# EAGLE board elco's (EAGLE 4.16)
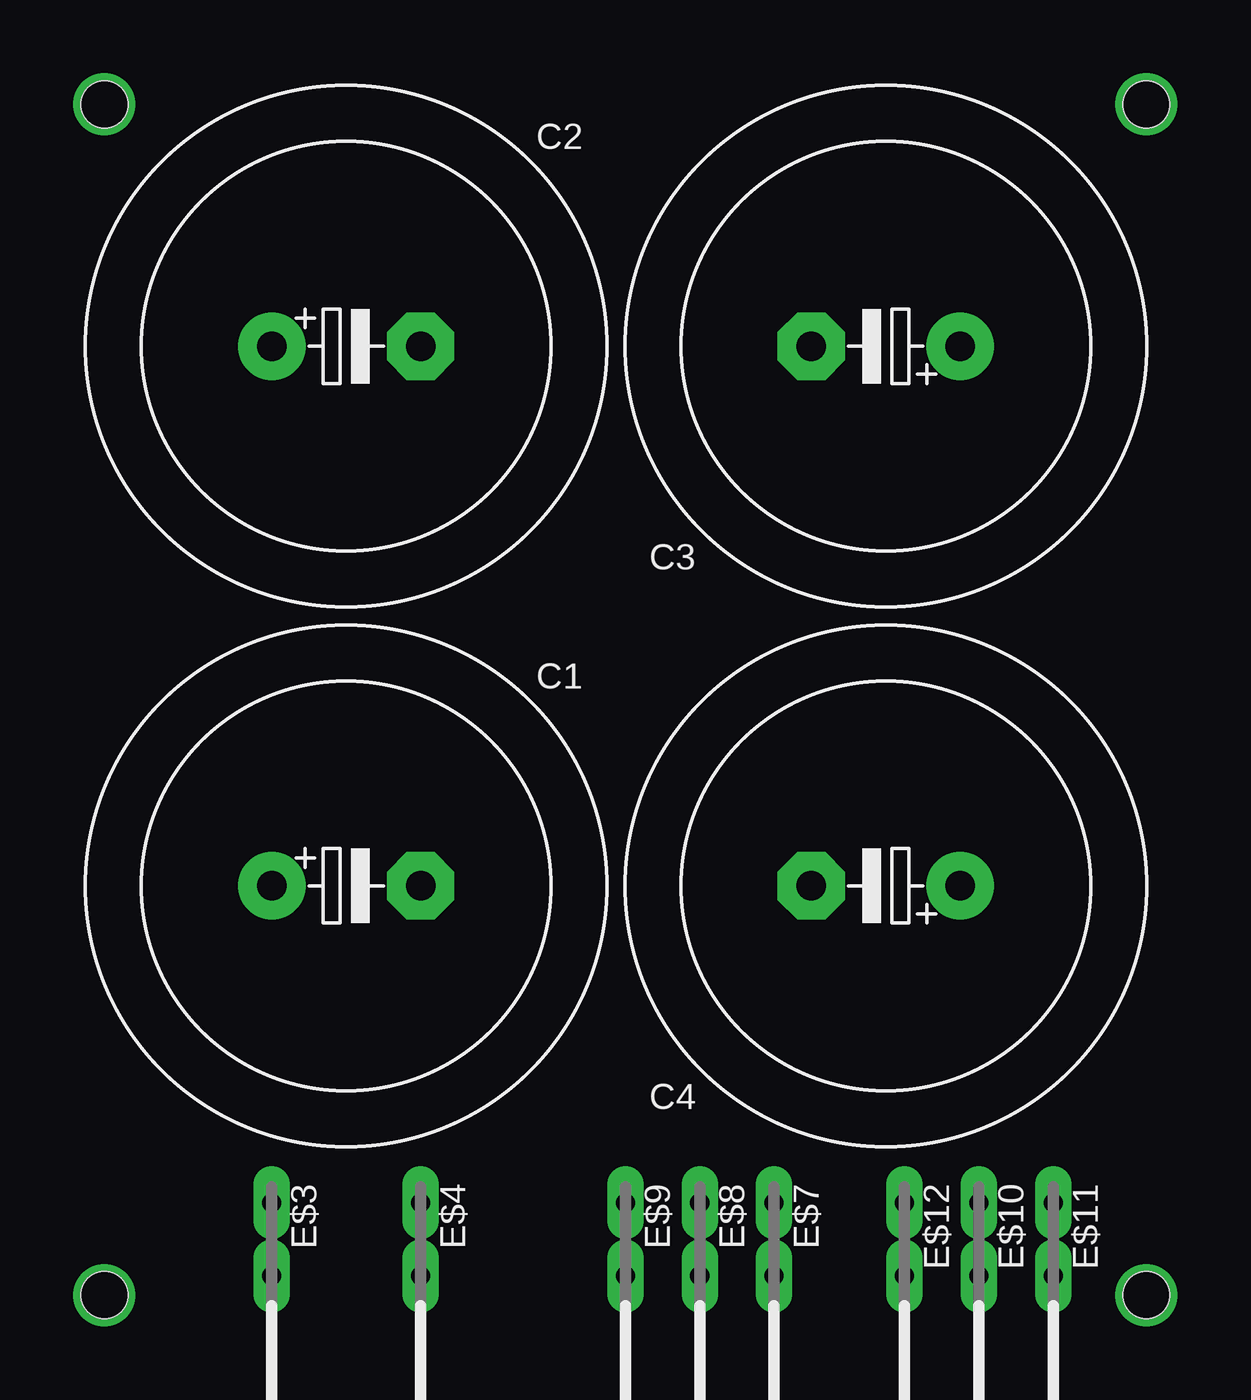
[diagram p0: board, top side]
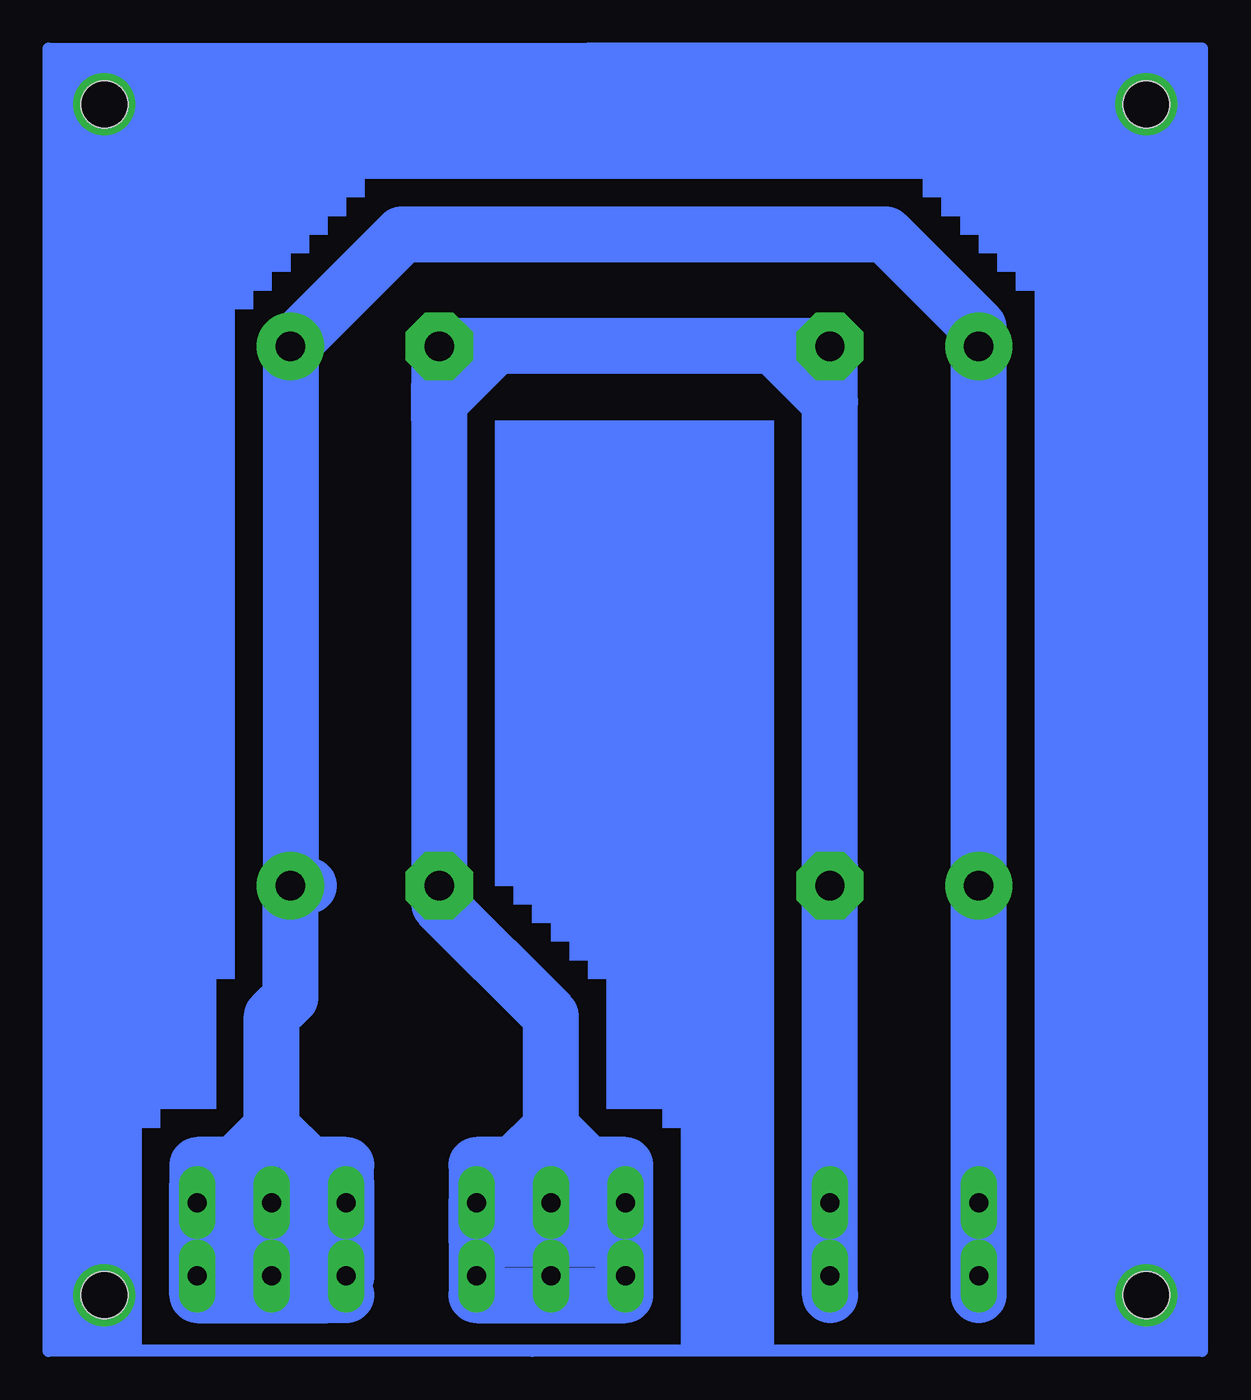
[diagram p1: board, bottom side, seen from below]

No outline drawn. Coordinates in mm, seen from the top.
Copper layers (1*16): Top 0.035mm / dielectric 1.5mm / Bottom 0.035mm
Design rules "default": minimum track width 10mil, minimum drill 24mil, track to track 8mil, track to pad 8mil, pad to pad 8mil, via to via 8mil, smd to smd 8mil, copper to edge 40mil, drill to drill 8mil, minimum pad ring 10mil, minimum via ring 8mil, stop-mask expansion 4mil, vias tented up to drill 0mil, thermal gap 10mil
Holes 3.2 mm at 3.81,-1.27 3.81,80.01 74.93,-1.27 74.93,80.01

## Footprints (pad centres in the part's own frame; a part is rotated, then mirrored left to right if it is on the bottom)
EB35D = drill 2.007 pad 4.597 round: + -5.08,0 | drill 2.007 pad 4.597 octagon: - 5.08,0
F061.200 = drill 1.3 pad 2.5 long: 1A -2.5,0; 1B 2.5,0

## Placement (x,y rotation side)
C1  4700µF 50V  [EB35D]  20.32,26.67 0 top
C2  4700µF 50V  [EB35D]  20.32,63.5 0 top
C3  4700µF 50V  [EB35D]  57.15,63.5 180 top
C4  4700µF 50V  [EB35D]  57.15,26.67 180 top
E$3  [F061.200]  15.24,2.54 270 top
E$4  [F061.200]  25.4,2.54 270 top
E$7  [F061.200]  49.53,2.54 270 top
E$8  [F061.200]  44.45,2.54 270 top
E$9  [F061.200]  39.37,2.54 270 top
E$10  [F061.200]  63.5,2.54 270 top
E$11  [F061.200]  68.58,2.54 270 top
E$12  [F061.200]  58.42,2.54 270 top

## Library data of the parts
C1-C4 = rcl
E$3 E$4 E$7-E$12 = con-faston

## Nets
S$2: C3.+ C4.+
S$5: C1.- C2.- C3.- C4.-

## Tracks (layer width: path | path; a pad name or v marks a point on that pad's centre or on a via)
C1+
  Bottom 0.813: 45.72,-5.08 0,-5.08 0,83.82 41.91,83.82
S$2
  Bottom 3.81: 15.24,-1.27 15.24,64.77 21.59,71.12 54.61,71.12 C3.+ C4.+ | 58.42,-1.27 59.69,-1.27 | 68.58,-1.27 68.58,2.54 | 68.58,2.54 68.58,6.35 58.42,6.35 | 58.42,6.35 58.42,0 | 58.42,6.35 58.42,7.62 59.69,7.62 | 59.69,7.62 63.5,7.62 | 63.5,7.62 66.04,7.62 | 66.04,7.62 68.58,7.62 68.58,2.54 | 68.58,2.54 59.69,2.54 59.69,5.08 62.23,5.08 68.58,-1.27 | 68.58,-1.27 59.69,-1.27 | 59.69,-1.27 60.96,-1.27 67.31,5.08 | 63.5,7.62 63.5,10.16 | 63.5,10.16 63.5,17.78 62.23,19.05 C4.+ | C4.+ 60.96,26.67 | 59.69,7.62 60.96,7.62 63.5,10.16 | 63.5,10.16 66.04,7.62
S$4  (via drill 3.2)
  other vias: 3.81,80.01
S$5
  Bottom 3.81: 39.37,-1.27 39.37,5.08 | 39.37,5.08 39.37,7.62 40.64,7.62 | 40.64,7.62 46.99,7.62 | 46.99,7.62 49.53,7.62 49.53,5.08 | 49.53,2.54 49.53,-1.27 39.37,-1.27 | 39.37,-1.27 39.37,1.27 40.64,2.54 49.53,2.54 | 49.53,2.54 49.53,5.08 | 49.53,5.08 39.37,5.08 | C1.- 25.4,27.94 | 25.4,27.94 25.4,59.69 | 25.4,59.69 C2.- 29.21,63.5 | 29.21,63.5 48.26,63.5 | 48.26,63.5 49.53,63.5 | 49.53,63.5 C3.- 52.07,60.96 | 52.07,58.42 52.07,60.96 | 52.07,58.42 52.07,27.94 | 52.07,27.94 C4.- | 29.21,63.5 26.67,60.96 | 25.4,59.69 29.21,63.5 | 49.53,63.5 52.07,60.96 | 52.07,58.42 52.07,59.69 48.26,63.5 | 25.4,-1.27 25.4,27.94 | 44.45,8.89 44.45,10.16 | 44.45,10.16 44.45,17.78 52.07,25.4 52.07,27.94 | 40.64,7.62 41.91,7.62 44.45,10.16 | 44.45,10.16 46.99,7.62
S$6  (via drill 3.2)
  other vias: 3.81,-1.27
S$10
  Bottom 0.813: 45.72,-5.08 78.74,-5.08 78.74,83.82 36.83,83.82
S$12  (via drill 3.2)
  other vias: 74.93,80.01
S$14  (via drill 3.2)
  other vias: 74.93,-1.27
(copper drawn outside any net)
  shapes: Bottom area x35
